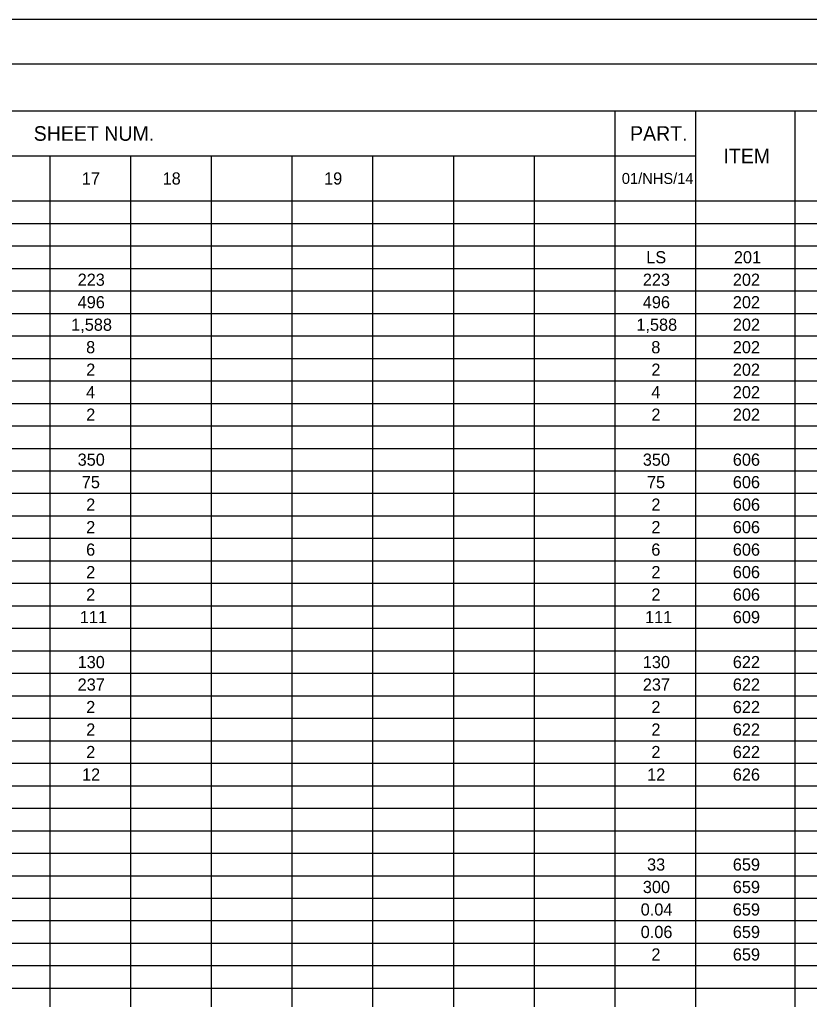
# Model space of a CAD drawing. Extents: x 0 to 34, y 0 to 22.
# Drawn here: x 8.03 to 16.98, y 10.89 to 22 of the extents above; entities that cross this region are included whole.
import ezdxf

# ---------------------------------------------------------------- set-up
doc = ezdxf.new("R2010")
doc.units = 0
for name, color, linetype in [('SH_Border', 7, 'Continuous'), ('SH_Cut_Line', 7, 'Continuous'), ('SH_Text', 7, 'Continuous')]:
    doc.layers.add(name, color=color, linetype=linetype)

msp = doc.modelspace()

# ---------------------------------------------------------------- linework, layer by layer
at = {"layer": 'SH_Border'}
msp.add_lwpolyline([(1.5, 21.5), (33.5, 21.5), (33.5, 0.5), (1.5, 0.5)], close=True, dxfattribs=at)
at = {"layer": 'SH_Cut_Line'}
msp.add_lwpolyline([(0, 0), (34, 0), (34, 22), (0, 22)], close=True, dxfattribs=at)
at = {"layer": 'SH_Text'}
for p, q in [((2.884, 20.964), (30.664, 20.964)), ((14.779, 20.964), (14.779, 1.839)), ((15.694, 20.964), (15.694, 1.839)), ((16.819, 20.964), (16.819, 1.839)), ((2.884, 20.454), (15.694, 20.454)), ((8.374, 20.454), (8.374, 1.839)), ((9.289, 20.454), (9.289, 1.839)), ((10.204, 20.454), (10.204, 1.839)), ((11.119, 20.454), (11.119, 1.839)), ((12.034, 20.454), (12.034, 1.839)), ((12.949, 20.454), (12.949, 1.839)), ((13.864, 20.454), (13.864, 1.839)), ((2.884, 19.944), (30.664, 19.944)), ((2.884, 19.689), (30.664, 19.689)), ((2.884, 19.434), (30.664, 19.434)), ((2.884, 19.179), (30.664, 19.179)), ((2.884, 18.924), (30.664, 18.924)), ((2.884, 18.669), (30.664, 18.669)), ((2.884, 18.414), (30.664, 18.414)), ((2.884, 18.159), (30.664, 18.159)), ((2.884, 17.904), (30.664, 17.904)), ((2.884, 17.649), (30.664, 17.649)), ((2.884, 17.394), (30.664, 17.394)), ((2.884, 17.139), (30.664, 17.139)), ((2.884, 16.884), (30.664, 16.884)), ((2.884, 16.629), (30.664, 16.629)), ((2.884, 16.374), (30.664, 16.374)), ((2.884, 16.119), (30.664, 16.119)), ((2.884, 15.864), (30.664, 15.864)), ((2.884, 15.609), (30.664, 15.609)), ((2.884, 15.354), (30.664, 15.354)), ((2.884, 15.099), (30.664, 15.099)), ((2.884, 14.844), (30.664, 14.844)), ((2.884, 14.589), (30.664, 14.589)), ((2.884, 14.334), (30.664, 14.334)), ((2.884, 14.079), (30.664, 14.079)), ((2.884, 13.824), (30.664, 13.824)), ((2.884, 13.569), (30.664, 13.569)), ((2.884, 13.314), (30.664, 13.314)), ((2.884, 13.059), (30.664, 13.059)), ((2.884, 12.804), (30.664, 12.804)), ((2.884, 12.549), (30.664, 12.549)), ((2.884, 12.294), (30.664, 12.294)), ((2.884, 12.039), (30.664, 12.039)), ((2.884, 11.784), (30.664, 11.784)), ((2.884, 11.529), (30.664, 11.529)), ((2.884, 11.274), (30.664, 11.274)), ((2.884, 11.019), (30.664, 11.019))]:
    msp.add_line(p, q, dxfattribs=at)

# ---------------------------------------------------------------- texts
for s, height, p in [('SHEET NUM.', 0.1656, (8.193, 20.626)), ('PART.', 0.1656, (14.951, 20.626)), ('ITEM', 0.1656, (16.009, 20.371)), ('17', 0.138, (8.739, 20.13)), ('18', 0.138, (9.654, 20.13)), ('19', 0.138, (11.484, 20.13)), ('01/NHS/14', 0.1242, (14.858, 20.137)), ('LS', 0.138, (15.135, 19.237)), ('201', 0.138, (16.128, 19.237)), ('223', 0.138, (8.691, 18.982)), ('223', 0.138, (15.096, 18.982)), ('202', 0.138, (16.116, 18.982)), ('496', 0.138, (8.691, 18.727)), ('496', 0.138, (15.096, 18.727)), ('202', 0.138, (16.116, 18.727)), ('1,588', 0.138, (8.618, 18.472)), ('1,588', 0.138, (15.023, 18.472)), ('202', 0.138, (16.116, 18.472)), ('8', 0.138, (8.787, 18.217)), ('8', 0.138, (15.192, 18.217)), ('202', 0.138, (16.116, 18.217)), ('2', 0.138, (8.788, 17.962)), ('2', 0.138, (15.193, 17.962)), ('202', 0.138, (16.116, 17.962)), ('4', 0.138, (8.787, 17.707)), ('4', 0.138, (15.192, 17.707)), ('202', 0.138, (16.116, 17.707)), ('2', 0.138, (8.788, 17.452)), ('2', 0.138, (15.193, 17.452)), ('202', 0.138, (16.116, 17.452)), ('350', 0.138, (8.691, 16.942)), ('350', 0.138, (15.096, 16.942)), ('606', 0.138, (16.116, 16.942)), ('75', 0.138, (8.738, 16.687)), ('75', 0.138, (15.143, 16.687)), ('606', 0.138, (16.116, 16.687)), ('2', 0.138, (8.788, 16.432)), ('2', 0.138, (15.193, 16.432)), ('606', 0.138, (16.116, 16.432)), ('2', 0.138, (8.788, 16.177)), ('2', 0.138, (15.193, 16.177)), ('606', 0.138, (16.116, 16.177)), ('6', 0.138, (8.787, 15.922)), ('6', 0.138, (15.192, 15.922)), ('606', 0.138, (16.116, 15.922)), ('2', 0.138, (8.788, 15.667)), ('2', 0.138, (15.193, 15.667)), ('606', 0.138, (16.116, 15.667)), ('2', 0.138, (8.788, 15.412)), ('2', 0.138, (15.193, 15.412)), ('606', 0.138, (16.116, 15.412)), ('111', 0.138, (8.716, 15.157)), ('111', 0.138, (15.121, 15.157)), ('609', 0.138, (16.116, 15.157)), ('130', 0.138, (8.691, 14.647)), ('130', 0.138, (15.096, 14.647)), ('622', 0.138, (16.116, 14.647)), ('237', 0.138, (8.691, 14.392)), ('237', 0.138, (15.096, 14.392)), ('622', 0.138, (16.116, 14.392)), ('2', 0.138, (8.788, 14.137)), ('2', 0.138, (15.193, 14.137)), ('622', 0.138, (16.116, 14.137)), ('2', 0.138, (8.788, 13.882)), ('2', 0.138, (15.193, 13.882)), ('622', 0.138, (16.116, 13.882)), ('2', 0.138, (8.788, 13.627)), ('2', 0.138, (15.193, 13.627)), ('622', 0.138, (16.116, 13.627)), ('12', 0.138, (8.74, 13.372)), ('12', 0.138, (15.145, 13.372)), ('626', 0.138, (16.116, 13.372)), ('33', 0.138, (15.144, 12.352)), ('659', 0.138, (16.116, 12.352)), ('300', 0.138, (15.096, 12.097)), ('659', 0.138, (16.116, 12.097)), ('0.04', 0.138, (15.072, 11.842)), ('659', 0.138, (16.116, 11.842)), ('0.06', 0.138, (15.072, 11.587)), ('659', 0.138, (16.116, 11.587)), ('2', 0.138, (15.193, 11.332)), ('659', 0.138, (16.116, 11.332))]:
    msp.add_text(s, height=height, dxfattribs=at).set_placement(p)

doc.saveas('drawing.dxf')
